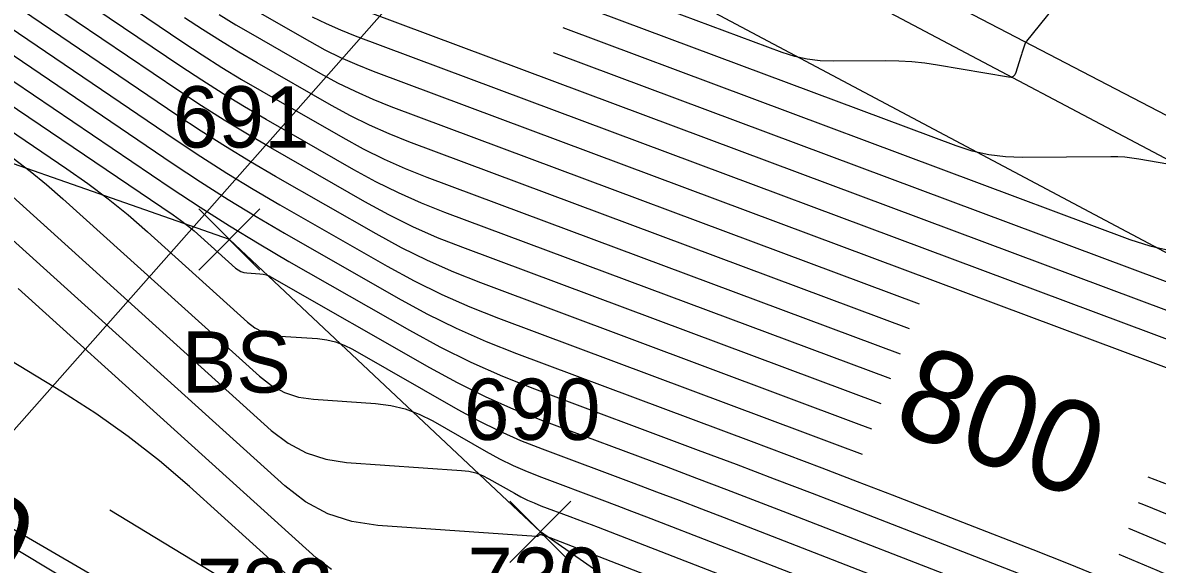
# Model space of a CAD drawing. Extents: x 1650836 to 1652450, y 332578 to 333908.
# Drawn here: x 1652100.04 to 1652137.1, y 332746.27 to 332763.95 of the extents above; entities that cross this region are included whole.
import ezdxf

# ---------------------------------------------------------------- set-up
doc = ezdxf.new("R2010")
doc.units = 0
for name, color, linetype in [('DCP', 7, 'Continuous'), ('DHW', 7, 'Continuous'), ('L_A', 7, 'Continuous'), ('L_I', 7, 'Continuous'), ('L_TIC', 7, 'Continuous'), ('LELB', 7, 'Continuous'), ('LSOGCMA', 7, 'Continuous'), ('LSOGCMA_T', 7, 'Continuous'), ('LSOGCMI', 7, 'Continuous'), ('PET', 7, 'Continuous'), ('RGR', 7, 'Continuous')]:
    doc.layers.add(name, color=color, linetype=linetype)

msp = doc.modelspace()

# ---------------------------------------------------------------- linework, layer by layer
at = {"layer": 'DCP'}
msp.add_lwpolyline([(1652097.436, 332748.039), (1652173.064, 332833.561)], dxfattribs=at)
at = {"layer": 'DHW'}
for points in [[(1652082.217, 332757.601), (1652081.771, 332756.62), (1652097.689, 332748.051), (1652112.113, 332739.371), (1652112.479, 332739.998)], [(1652112.479, 332739.998), (1652082.217, 332757.601)]]:
    msp.add_lwpolyline(points, dxfattribs=at)
at = {"layer": 'L_TIC'}
for points in [[(1652105.793, 332755.875), (1652107.793, 332757.875)], [(1652107.793, 332755.875), (1652105.793, 332757.875)], [(1652115.951, 332746.33), (1652117.951, 332748.33)], [(1652117.951, 332746.33), (1652115.951, 332748.33)]]:
    msp.add_lwpolyline(points, dxfattribs=at)
at = {"layer": 'LELB'}
for points in [[(1651844.759, 332915.941), (1651880.379, 332894.976), (1651917.082, 332874.787), (1651949.824, 332853.945), (1651967.074, 332844.342), (1652000.53, 332828.254), (1652035.357, 332809.776), (1652067.23, 332793.489), (1652106.029, 332773.108), (1652143.274, 332753.324), (1652172.167, 332734.049)], [(1652048.756, 332662.461), (1652082.555, 332678.298), (1652130.366, 332703.201), (1652148.083, 332715.406), (1652159.47, 332726.367), (1652148.02, 332734.227), (1652128.413, 332739.339), (1652116.951, 332747.33), (1652106.793, 332756.875), (1652094.604, 332761.138), (1652083.802, 332764.466), (1652074.482, 332770.284), (1652065.17, 332770.428), (1652062.989, 332774.387), (1652054.537, 332784.724), (1652034.993, 332796.475), (1652025.062, 332801.1), (1652009.772, 332808.074), (1651988.967, 332816.401), (1651980.006, 332832.954), (1651960.575, 332843.477), (1651932.852, 332862.75), (1651890.753, 332886.019), (1651847.527, 332911.35)]]:
    msp.add_lwpolyline(points, dxfattribs=at)
at = {"layer": 'LSOGCMA'}
for points in [[(1652135.443, 332766.589), (1652132.832, 332763.352), (1652132.819, 332763.334), (1652132.808, 332763.316), (1652132.799, 332763.297), (1652132.79, 332763.277), (1652132.674, 332762.951), (1652132.662, 332762.917), (1652132.651, 332762.883), (1652132.64, 332762.849), (1652132.63, 332762.815), (1652132.487, 332762.323), (1652132.451, 332762.243), (1652132.398, 332762.191), (1652132.328, 332762.166), (1652132.241, 332762.169), (1652129.925, 332762.568), (1652129.506, 332762.631), (1652129.086, 332762.674), (1652128.664, 332762.699), (1652128.241, 332762.705), (1652126.515, 332762.69), (1652126.089, 332762.705), (1652125.671, 332762.759), (1652125.258, 332762.851), (1652124.853, 332762.982), (1652118.299, 332765.43)], [(1652128.394, 332752.32), (1652113.831, 332757.759), (1652113.067, 332758.062), (1652112.317, 332758.395), (1652111.581, 332758.758), (1652110.859, 332759.152), (1652108, 332760.785), (1652107.289, 332761.2), (1652106.587, 332761.629), (1652105.893, 332762.07), (1652105.207, 332762.525), (1652100.525, 332765.691)], [(1652127.568, 332743.135), (1652117.267, 332747.13), (1652117.236, 332747.142), (1652117.205, 332747.153), (1652117.173, 332747.165), (1652117.142, 332747.176), (1652116.98, 332747.234), (1652116.967, 332747.237), (1652116.953, 332747.237), (1652116.941, 332747.233), (1652116.928, 332747.226), (1652116.88, 332747.191), (1652116.868, 332747.184), (1652116.855, 332747.179), (1652116.841, 332747.176), (1652116.826, 332747.176), (1652111.638, 332747.536), (1652110.796, 332747.662), (1652110.01, 332747.919), (1652109.28, 332748.306), (1652108.605, 332748.825), (1652095.297, 332760.837)], [(1652137.485, 332748.847), (1652136.804, 332749.115)]]:
    msp.add_lwpolyline(points, dxfattribs=at)
at = {"layer": 'LSOGCMI'}
for points in [[(1652100.938, 332766.248), (1652105.269, 332763.32), (1652105.903, 332762.899), (1652106.545, 332762.491), (1652107.195, 332762.095), (1652107.852, 332761.711), (1652110.496, 332760.2), (1652111.164, 332759.836), (1652111.845, 332759.5), (1652112.538, 332759.192), (1652113.245, 332758.912), (1652128.704, 332753.139)], [(1652128.084, 332751.502), (1652114.417, 332756.606), (1652113.595, 332756.932), (1652112.789, 332757.29), (1652111.998, 332757.681), (1652111.222, 332758.103), (1652108.148, 332759.86), (1652107.384, 332760.306), (1652106.629, 332760.767), (1652105.883, 332761.241), (1652105.145, 332761.73), (1652100.112, 332765.134)], [(1652141.468, 332753.042), (1652110.315, 332764.675)], [(1652097.641, 332764.325), (1652098.253, 332763.889), (1652098.872, 332763.463), (1652104.96, 332759.345), (1652105.852, 332758.754), (1652106.755, 332758.18), (1652107.668, 332757.623), (1652108.592, 332757.084), (1652112.31, 332754.959), (1652113.249, 332754.447), (1652114.206, 332753.975), (1652115.181, 332753.542), (1652116.175, 332753.148), (1652123.836, 332750.287), (1652124.99, 332749.853), (1652126.143, 332749.417), (1652127.295, 332748.976), (1652128.445, 332748.533), (1652133.042, 332746.75), (1652134.188, 332746.298), (1652135.33, 332745.832), (1652136.465, 332745.354), (1652137.596, 332744.862)], [(1652127.774, 332750.683), (1652127.363, 332750.838), (1652115.003, 332755.453), (1652114.124, 332755.802), (1652113.261, 332756.185), (1652112.415, 332756.603), (1652111.585, 332757.055), (1652108.296, 332758.934), (1652107.479, 332759.412), (1652106.671, 332759.904), (1652105.872, 332760.412), (1652105.083, 332760.935), (1652099.698, 332764.577)], [(1652107.408, 332764.487), (1652109.408, 332763.344), (1652109.913, 332763.069), (1652110.428, 332762.815), (1652110.952, 332762.582), (1652111.487, 332762.37), (1652137.942, 332752.491)], [(1652137.767, 332759.28), (1652136.502, 332759.498), (1652136.273, 332759.532), (1652136.043, 332759.556), (1652135.813, 332759.569), (1652135.582, 332759.572), (1652132.694, 332759.547), (1652132.14, 332759.567), (1652131.595, 332759.637), (1652131.059, 332759.757), (1652130.531, 332759.928), (1652117.993, 332764.61)], [(1652099.285, 332764.02), (1652105.022, 332760.14), (1652105.862, 332759.583), (1652106.713, 332759.042), (1652107.574, 332758.518), (1652108.444, 332758.009), (1652111.947, 332756.007), (1652112.832, 332755.525), (1652113.734, 332755.08), (1652114.653, 332754.672), (1652115.589, 332754.3), (1652125.599, 332750.562), (1652126.649, 332750.168), (1652127.462, 332749.86)], [(1652129.014, 332753.957), (1652112.659, 332760.064), (1652112.01, 332760.322), (1652111.372, 332760.605), (1652110.747, 332760.914), (1652110.133, 332761.248), (1652107.704, 332762.636), (1652107.1, 332762.989), (1652106.503, 332763.353), (1652105.913, 332763.728), (1652105.33, 332764.114)], [(1652106.461, 332764.215), (1652107.005, 332763.883), (1652107.556, 332763.562), (1652109.771, 332762.296), (1652110.33, 332761.991), (1652110.9, 332761.71), (1652111.481, 332761.452), (1652112.073, 332761.217), (1652129.323, 332754.775)], [(1652109.496, 332764.147), (1652109.955, 332763.92), (1652110.424, 332763.712), (1652110.901, 332763.523), (1652139.705, 332752.766)], [(1652117.687, 332763.79), (1652136.209, 332756.873), (1652136.859, 332756.663), (1652137.52, 332756.515)], [(1652098.458, 332762.906), (1652104.898, 332758.55), (1652105.842, 332757.925), (1652106.797, 332757.318), (1652107.763, 332756.729), (1652108.74, 332756.158), (1652112.673, 332753.911), (1652113.666, 332753.37), (1652114.678, 332752.87), (1652115.71, 332752.412), (1652116.761, 332751.995), (1652122.104, 332749.999), (1652123.347, 332749.533), (1652124.589, 332749.062), (1652125.83, 332748.588), (1652127.069, 332748.11), (1652132.114, 332746.153), (1652133.364, 332745.66), (1652134.609, 332745.153), (1652135.848, 332744.631), (1652137.08, 332744.094), (1652143.616, 332741.207)], [(1652143.231, 332753.317), (1652117.381, 332762.971)], [(1652098.045, 332762.349), (1652104.958, 332757.673), (1652105.195, 332757.507), (1652105.425, 332757.333), (1652105.649, 332757.151), (1652105.867, 332756.961), (1652106.999, 332755.94), (1652107.081, 332755.877), (1652107.17, 332755.83), (1652107.265, 332755.798), (1652107.368, 332755.783), (1652107.791, 332755.754), (1652107.895, 332755.741), (1652107.995, 332755.716), (1652108.093, 332755.681), (1652108.186, 332755.634), (1652113.333, 332752.693), (1652114.23, 332752.204), (1652115.144, 332751.752), (1652116.077, 332751.338), (1652117.026, 332750.962), (1652121.056, 332749.457), (1652122.047, 332749.085), (1652123.036, 332748.71), (1652124.024, 332748.332), (1652125.011, 332747.951), (1652131.186, 332745.557)], [(1652097.632, 332761.792), (1652101.49, 332759.182), (1652102.174, 332758.702), (1652102.84, 332758.199), (1652103.487, 332757.673), (1652104.117, 332757.124), (1652107.387, 332754.173), (1652107.624, 332753.991), (1652107.881, 332753.855), (1652108.157, 332753.764), (1652108.453, 332753.72), (1652109.675, 332753.635), (1652109.976, 332753.598), (1652110.266, 332753.528), (1652110.547, 332753.425), (1652110.818, 332753.289), (1652114.256, 332751.324), (1652114.924, 332750.96), (1652115.606, 332750.624), (1652116.3, 332750.315), (1652117.007, 332750.035), (1652120.009, 332748.914), (1652120.746, 332748.637), (1652121.483, 332748.358), (1652122.219, 332748.077), (1652122.954, 332747.793), (1652130.257, 332744.961)], [(1652098.324, 332759.521), (1652108.164, 332750.639), (1652108.711, 332750.219), (1652109.303, 332749.904), (1652109.941, 332749.696), (1652110.623, 332749.594), (1652114.376, 332749.334), (1652114.611, 332749.304), (1652114.839, 332749.25), (1652115.059, 332749.169), (1652115.271, 332749.063), (1652116.103, 332748.587), (1652116.314, 332748.472), (1652116.528, 332748.367), (1652116.746, 332748.27), (1652116.969, 332748.181), (1652117.913, 332747.829), (1652118.145, 332747.742), (1652118.377, 332747.654), (1652118.609, 332747.565), (1652118.84, 332747.476), (1652128.401, 332743.768)], [(1652099.728, 332759.523), (1652100.284, 332759.103), (1652100.825, 332758.664), (1652101.351, 332758.205), (1652107.775, 332752.406), (1652108.168, 332752.105), (1652108.592, 332751.879), (1652109.049, 332751.73), (1652109.538, 332751.657), (1652111.571, 332751.516), (1652112.063, 332751.455), (1652112.538, 332751.34), (1652112.997, 332751.172), (1652113.44, 332750.95), (1652115.18, 332749.956), (1652115.619, 332749.716), (1652116.067, 332749.495), (1652116.523, 332749.293), (1652116.988, 332749.108), (1652118.961, 332748.371), (1652119.446, 332748.189), (1652119.93, 332748.006), (1652120.414, 332747.821), (1652120.897, 332747.634), (1652129.329, 332744.365)], [(1652110.664, 332744.134), (1652105.489, 332748.805), (1652104.507, 332749.65), (1652103.489, 332750.446), (1652102.434, 332751.192), (1652101.342, 332751.89), (1652089.592, 332759.014)], [(1652110.13, 332746.099), (1652109.634, 332746.479), (1652099.898, 332755.268)], [(1652107.659, 332745.145), (1652102.89, 332748.036)], [(1652137.491, 332747.871), (1652136.661, 332748.21), (1652136.487, 332748.278)], [(1652137.701, 332746.8), (1652136.771, 332747.191), (1652136.168, 332747.437)], [(1652135.849, 332746.594), (1652136.05, 332746.512), (1652137.083, 332746.077), (1652138.111, 332745.63)]]:
    msp.add_lwpolyline(points, dxfattribs=at)
at = {"layer": 'PET'}
msp.add_lwpolyline([(1651764.546, 332972.615), (1651784.506, 332958.597), (1651809.702, 332941.927), (1651846.26, 332918.158), (1651881.765, 332897.162), (1651918.116, 332876.642), (1651951.432, 332858.415), (1651975.296, 332845.48), (1652002.223, 332831.337), (1652037.173, 332813.417), (1652069.296, 332796.636), (1652107.428, 332776.545), (1652145.079, 332756.921), (1652175.234, 332740.226), (1652190.754, 332731.861), (1652206.573, 332723.523), (1652239.422, 332706.921), (1652282.404, 332684.366), (1652332.494, 332658.525), (1652365.542, 332641.171), (1652388.914, 332629.021)], dxfattribs=at)
at = {"layer": 'RGR'}
msp.add_lwpolyline([(1651963.926, 332842.71), (1651967.074, 332844.342), (1651975.028, 332844.451), (1652001.752, 332830.477), (1652036.76, 332812.304), (1652068.698, 332795.548), (1652107.135, 332775.504), (1652144.421, 332755.8), (1652165.98, 332744.268), (1652170.761, 332738.792), (1652172.167, 332734.049)], dxfattribs=at)

# ---------------------------------------------------------------- texts
at = {"layer": 'L_A'}
msp.add_text('BS', height=2, dxfattribs=at).set_placement((1652105.234, 332751.875))
at = {"layer": 'L_I'}
for s, p in [('691', (1652104.951, 332759.875)), ('690', (1652114.455, 332750.33)), ('730', (1652114.566, 332744.812)), ('733', (1652105.733, 332744.456))]:
    msp.add_text(s, height=2, dxfattribs=at).set_placement(p)
at = {"layer": 'LSOGCMA_T'}
for s, rotation, p in [('800', 339.2615, (1652128.368, 332750.719)), ('790', 330.4332, (1652093.449, 332748.532))]:
    msp.add_text(s, height=3, rotation=rotation, dxfattribs=at).set_placement(p)

doc.saveas('drawing.dxf')
